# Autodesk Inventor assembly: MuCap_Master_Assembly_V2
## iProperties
Shininess: 64.0
Length Units: 11269
Angle Units: 11279
Time Units: 11290
Mass Units: 11283
Length Display Precision: 3
Angle Display Precision: 2
Compacted: True
Created: 2004-08
Part Number: MuCap_Master_Assembly_V2
Document SubType Name: Assembly
Designer: John Blackburn
Manufacturer: Standard
Standards Organization: Custom
Density: 0.0
Volumn: 0.0
Area: 0.0
PropertySet Name: Model Information
Control State: 0
Master: False
Checked Out: False
Author: John Blackburn
